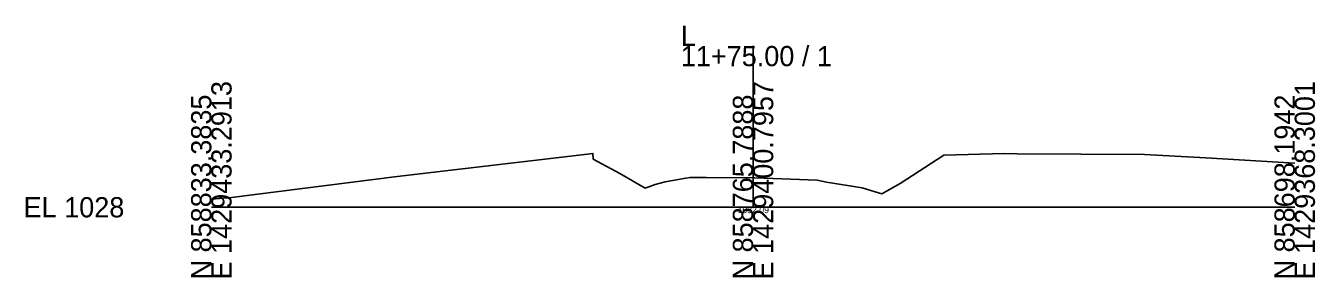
# Model space of a CAD drawing. Extents: x -26 to 153, y -10 to 13058.
# Drawn here: x -25.7 to 152.8, y 490.3 to 525.1 of the extents above; entities that cross this region are included whole.
import ezdxf

# ---------------------------------------------------------------- set-up
doc = ezdxf.new("R2010")
doc.units = 0
for name, color, linetype in [('Default', 7, 'Continuous'), ('Exist Cross Section Cell', 7, 'Continuous'), ('Exist XS Center Line Elevation Label', 7, 'Continuous'), ('Exist XS Ground Line', 7, 'Continuous')]:
    doc.layers.add(name, color=color, linetype=linetype)

msp = doc.modelspace()

# ---------------------------------------------------------------- linework, layer by layer
at = {"layer": 'Exist Cross Section Cell'}
for p, q in [((75, 500), (75, 522.34)), ((0, 500), (75, 500)), ((75, 500), (150, 500))]:
    msp.add_line(p, q, dxfattribs=at)
at = {"layer": 'Exist XS Ground Line'}
msp.add_lwpolyline([(0, 501.11), (2.78, 501.34), (25.73, 504.28), (52.09, 507.36), (52.84, 507.45), (52.87, 506.67), (56.58, 504.67), (60.05, 502.65), (61.43, 503.14), (62.83, 503.54), (65.69, 504.04), (66.28, 504.14), (68.52, 504.13), (75.25, 504.09), (77.72, 503.99), (83.9, 503.74), (85.18, 503.48), (90.12, 502.68), (91.93, 502.13), (92.83, 501.88), (95.35, 503.3), (101.44, 507.2), (109.8, 507.44), (111.58, 507.4), (129.21, 507.33), (137.68, 506.83), (150, 506.12)], dxfattribs=at)
msp.add_lwpolyline([(0, 501.11), (2.78, 501.34), (25.73, 504.28), (52.09, 507.36), (52.84, 507.45), (52.87, 506.67), (56.58, 504.67), (60.05, 502.65), (61.43, 503.14), (62.83, 503.54), (65.69, 504.04), (66.28, 504.14), (68.52, 504.13), (75.25, 504.09), (77.72, 503.99), (83.9, 503.74), (85.18, 503.48), (90.12, 502.68), (91.93, 502.13), (92.83, 501.88), (95.35, 503.3), (101.44, 507.2), (109.8, 507.44), (111.58, 507.4), (129.21, 507.33), (137.68, 506.83), (150, 506.12)], dxfattribs=at)
msp.add_lwpolyline([(0, 501.11), (2.78, 501.34), (25.73, 504.28), (52.09, 507.36), (52.84, 507.45), (52.87, 506.67), (56.58, 504.67), (60.05, 502.65), (61.43, 503.14), (62.83, 503.54), (65.69, 504.04), (66.28, 504.14), (68.52, 504.13), (75.25, 504.09), (77.72, 503.99), (83.9, 503.74), (85.18, 503.48), (90.12, 502.68), (91.93, 502.13), (92.83, 501.88), (95.35, 503.3), (101.44, 507.2), (109.8, 507.44), (111.58, 507.4), (129.21, 507.33), (137.68, 506.83), (150, 506.12)], dxfattribs=at)

# ---------------------------------------------------------------- texts
at = {"layer": 'Default'}
msp.add_text('-', height=0.0001, dxfattribs=at).set_placement((0, 500))
at = {"layer": 'Exist Cross Section Cell'}
for s, p in [('L', (65, 522.34)), ('11+75.00 / 1', (65, 519.54)), ('EL 1028', (-26, 498.6))]:
    msp.add_text(s, height=2.8, dxfattribs=at).set_placement(p)
for s, p in [('E 1429433.2913', (2.8, 490)), ('E 1429400.7957', (77.8, 490)), ('E 1429368.3001', (152.8, 490)), ('N 858833.3835', (0, 490)), ('N 858765.7888', (75, 490)), ('N 858698.1942', (150, 490))]:
    msp.add_text(s, height=2.8, rotation=90, dxfattribs=at).set_placement(p)
at = {"layer": 'Exist XS Center Line Elevation Label'}
msp.add_text('1032.09', height=0.9, dxfattribs=at).set_placement((72.86, 499.19))
msp.add_text('1032.09', height=0.9, dxfattribs=at).set_placement((72.86, 499.19))
msp.add_text('1032.09', height=0.9, dxfattribs=at).set_placement((72.86, 499.19))

doc.saveas('drawing.dxf')
